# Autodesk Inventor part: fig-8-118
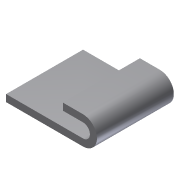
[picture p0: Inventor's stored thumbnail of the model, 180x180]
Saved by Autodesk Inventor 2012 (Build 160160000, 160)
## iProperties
Created: 2009-09
Part Number: fig-8-118
Document SubType Name: Modeling
Designer: Sham
Density: 1 g/cm^3
Material: Default
Author: Sham
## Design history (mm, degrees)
sketch "Sketch1"
  geometry: L1 (-33.976, 22)-(0, 22); L2 (0, 22)-(0, 0); L3 (0, 0)-(-33.976, 0); L4 (-33.976, 0)-(-33.976, 22)
  constraints: 8 end point, 2 parallel, 1 horizontal, 1 perpendicular
extrude "Extrusion1" new body sketch "Sketch1" distance "d0" = 2; taper "d1" = 0 deg
sketch "Sketch2"
  geometry: L1 (-12, 22)-(-12, 0)
  constraints: 2 end point
feature "Bend Part1" sketch "Sketch2" dims "d2" = 2, "d3" = 180 deg
body "Solid1"
